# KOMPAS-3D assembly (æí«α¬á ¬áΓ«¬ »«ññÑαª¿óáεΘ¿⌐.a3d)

Referenced files in D:\МОДЕЛЬ ТАНКА Т90\ДЕТАЛИ\ХОДОВАЯ\Каток поддерживающий\: каток поддерживающий.m3d, ось катка поддерж.m3d, крышка катка поддержив.m3d
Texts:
  Сборка каток поддерживающий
